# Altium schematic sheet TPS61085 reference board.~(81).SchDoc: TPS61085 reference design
size A4; Date: Not shown in title block; ApprovedBy: Not shown in title block; CheckedBy: Not shown in title block; Author: Not shown in title block; CompanyName: Not shown in title block; DrawnBy: Helen Chen; Engineer: Not shown in title block; Organization: Not shown in title block; Address1: Not shown in title block; Address2: Not shown in title block; Address3: Not shown in title block; Address4: Not shown in title block; DocumentNumber: 1; Revision: Use project parameter SCH_Rev; SheetNumber: 1; SheetTotal: 2; PageSetup: Record=PageOptions¦CenterHorizontal=True¦CenterVertical=True¦PrintScale=0.91¦XCorrection=1.00¦YCorrection=1.00¦PrintKind=0¦BorderSize=5000000¦LeftOffset=0¦BottomOffset=0¦Orientation=2¦PaperLength=1000¦PaperWidth=1000¦Scale=100¦PaperSource=15¦PrintQuality=600¦MediaType=1¦DitherType=10¦PrintScaleMode=1¦PaperKind=Letter
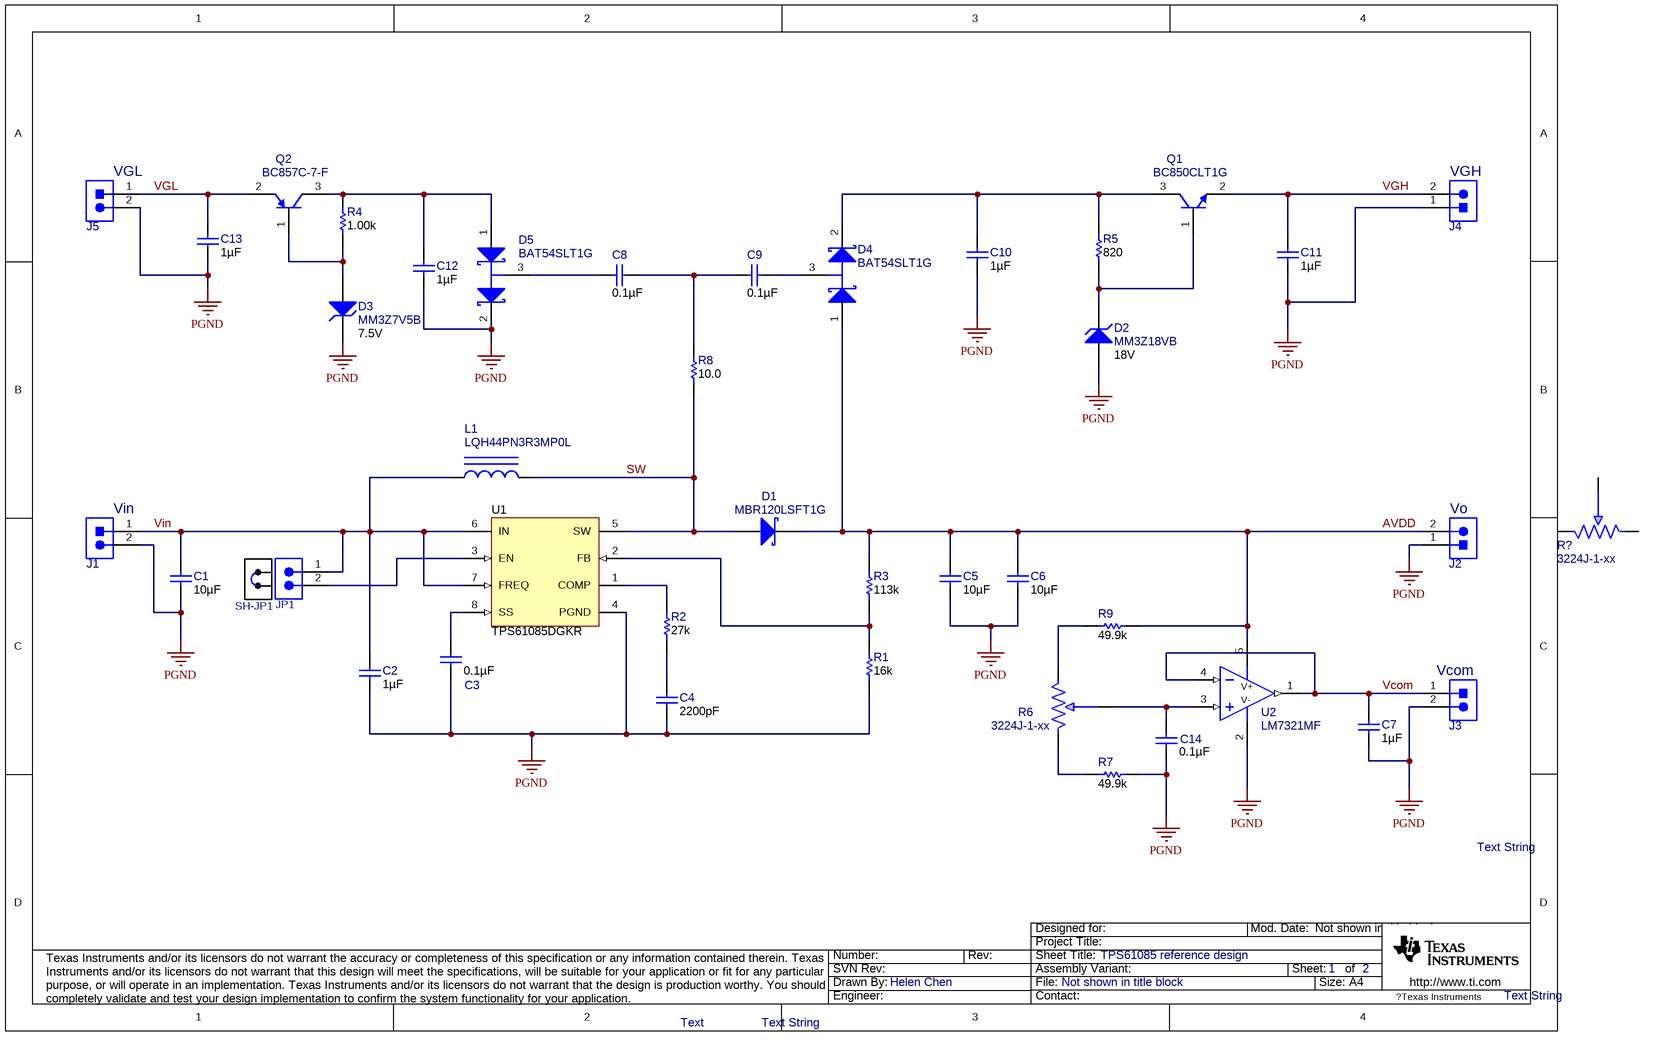
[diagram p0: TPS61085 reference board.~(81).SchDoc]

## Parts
C1  ValueDisplayed: 10µF  [0805_HV]  (hidden comment: GRM219R61A106KE44D)
C2  ValueDisplayed: 1µF  [0603]  (hidden comment: GRM185R61C105KE44D)
C3  ValueDisplayed: 0.1µF  [0402]  (hidden comment: GRM155R71C104KA88D)
C4  ValueDisplayed: 2200pF  [0402]  (hidden comment: GRM155R61C222KA01D)
C5  ValueDisplayed: 10µF  [0805_HV]  (hidden comment: C2012X5R1E106K125AB)
C6  ValueDisplayed: 10µF  [0805_HV]  (hidden comment: C2012X5R1E106K125AB)
C7  ValueDisplayed: 1µF  [0603]  (hidden comment: GRM185R61C105KE44D)
C8  ValueDisplayed: 0.1µF  [0603]  (hidden comment: 06035C104KAT2A)
C9  ValueDisplayed: 0.1µF  [0603]  (hidden comment: 06035C104KAT2A)
C10  ValueDisplayed: 1µF  [0603]  (hidden comment: GRM188R61H105KAALD)
C11  ValueDisplayed: 1µF  [0603]  (hidden comment: GRM188R61H105KAALD)
C12  ValueDisplayed: 1µF  [0603]  (hidden comment: GRM185R61C105KE44D)
C13  ValueDisplayed: 1µF  [0603]  (hidden comment: GRM185R61C105KE44D)
C14  ValueDisplayed: 0.1µF  [0402]  (hidden comment: GRM155R71C104KA88D)
D1  MBR120LSFT1G  [SOD-123FL]
D2  MM3Z18VB  value 18V  [SOD-323F]
D3  MM3Z7V5B  value 7.5V  [SOD-323F]
D4  BAT54SLT1G  [SOT-23]
D5  BAT54SLT1G  [SOT-23]
J1  ED555/2DS  [TERM_BLK_ED555-2DS]  (value not drawn)
J2  ED555/2DS  [TERM_BLK_ED555-2DS]  (value not drawn)
J3  ED555/2DS  [TERM_BLK_ED555-2DS]  (value not drawn)
J4  ED555/2DS  [TERM_BLK_ED555-2DS]  (value not drawn)
J5  ED555/2DS  [TERM_BLK_ED555-2DS]  (value not drawn)
JP1  PEC02SAAN  [CONN_PEC02SAAN]  (value not drawn)
L1  LQH44PN3R3MP0L  [IND_LQH44P]
Q1  BC850CLT1G  [SOT-23]
Q2  BC857C-7-F  [SOT-23]
R1  ValueDisplayed: 16k  [0402]  (hidden comment: CRCW040216K0JNED)
R2  ValueDisplayed: 27k  [0402]  (hidden comment: CRCW040227K0JNED)
R3  ValueDisplayed: 113k  [0402]  (hidden comment: CRCW0402113KFKED)
R4  ValueDisplayed: 1.00k  [0603]  (hidden comment: RC0603FR-071KL)
R5  ValueDisplayed: 820  [0603]  (hidden comment: RC0603FR-07820RL)
R6  3224J-1-xx  [POT_2MM-SQ]
R7  ValueDisplayed: 49.9k  [0402]  (hidden comment: CRCW040249K9FKED)
R8  ValueDisplayed: 10.0  [0603]  (hidden comment: CRCW060310R0FKEA)
R9  ValueDisplayed: 49.9k  [0402]  (hidden comment: CRCW040249K9FKED)
R?  3224J-1-xx  [POT_2MM-SQ]
SH-JP1  969102-0000-DA  [SNT-100-BK-G]  (value not drawn)
U1  TPS61085DGKR  [DGK0008A_N]
U2  LM7321MF  [MF05A_L]

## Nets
PGND: C1.2 C2.2 C3.2 C4.2 C5.2 C6.2 C7.2 C10.2 C11.2 C12.2 C13.2 C14.2 D2.2(A) D3.1(K) D5.2(K) J1.2 J2.1 J3.2 J4.1 J5.2 R1.1 R7.2 U1.4(PGND) U2.2(V-)
AVDD: C5.1 C6.1 D1.1(K) D4.1(A) J2.2 R3.2 R9.2 U2.5(V+)
SW: D1.2(A) L1.2 R8.1 U1.5(SW)
Vcom: C7.1 J3.1 U2.1(OUT) U2.4(IN-)
VGH: C11.1 J4.2 Q1.2(E)
VGL: C13.1 J5.1 Q2.2(E)
Vin: C1.1 C2.1 J1.1 JP1.1 L1.1 U1.6(IN) U1.7(FREQ)
NetC3_1: C3.1 U1.8(SS)
NetC4_1: C4.1 R2.1
NetC8_1: C8.1 C9.2 R8.2
NetC8_2: C8.2 D5.3(C)
NetC9_1: C9.1 D4.3(C)
NetC10_1: C10.1 D4.2(K) Q1.3(C) R5.2
NetC12_1: C12.1 D5.1(A) Q2.3(C) R4.2
NetC14_1: C14.1 R6.2 U2.3(IN+)
NetD2_1: D2.1(K) Q1.1(B) R5.1
NetD3_2: D3.2(A) Q2.1(B) R4.1
NetJP1_2: JP1.2 U1.3(EN)
NetR1_2: R1.2 R3.1 U1.2(FB)
NetR2_2: R2.2 U1.1(COMP)
NetR6_1: R6.1 R9.1
NetR6_3: R6.3 R7.1

Not connected (* = marked no-connect by the designer): R? 1 2 3

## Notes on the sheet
- (near J5) VGL
- (near J4) VGH
- (near J1) Vin
- (near J2) Vo
- (near J3) Vcom
- Text String
- Text

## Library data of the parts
C1 = GRM219R61A106KE44D: CAP, CERM, 10 µF, 10 V, +/- 10%, X5R, 0805; Manufacturer: MuRata; Polarized: N; CompType: Capacitor; Value: 10uF; U/M: EA; Cap_F: 0.00001; Tolerance_%: 10; ESR_ohm: 0.005; Value1: 0.005 ohm; Value2: 10V; TaMin_C: -55; TaMax_C: 85; Cap_Case: 0805
C2 C7 C12 C13 = GRM185R61C105KE44D: CAP, CERM, 1 µF, 16 V, +/- 10%, X5R, 0603; Manufacturer: MuRata; Polarized: N; CompType: Capacitor; Value: 1uF; U/M: EA; Cap_F: 0.000001; Tolerance_%: 10; Value1: Unknown; VDC_V: 16; Value2: 16V; TaMin_C: -55; TaMax_C: 85
C3 C14 = GRM155R71C104KA88D: CAP, CERM, 0.1 µF, 16 V, +/- 10%, X7R, 0402; Manufacturer: MuRata; Polarized: N; CompType: Capacitor; Value: 0.1uF; U/M: EA; Cap_F: 0.0000001; Tolerance_%: 10; Value1: Unknown; VDC_V: 16; Value2: 16V; TaMin_C: -55; TaMax_C: 125
C4 = GRM155R61C222KA01D: CAP, CERM, 2200 pF, 16 V, +/- 10%, X5R, 0402; Manufacturer: MuRata; Polarized: N; CompType: Capacitor; Value: 2200pF; U/M: EA; Cap_F: 0.0000000022; Tolerance_%: 10; Value1: Unknown; VDC_V: 16; Value2: 16V; TaMin_C: -55; TaMax_C: 85
C5 C6 = C2012X5R1E106K125AB: CAP, CERM, 10 µF, 25 V, +/- 10%, X5R, 0805; Manufacturer: TDK; Polarized: N; CompType: Capacitor; Value: 10uF; U/M: EA; Cap_F: 0.00001; Tolerance_%: 10; Value1: Unknown; VDC_V: 25; Value2: 25V; TaMin_C: -55; TaMax_C: 85; Cap_Case: 0805
C8 C9 = 06035C104KAT2A: CAP, CERM, 0.1 µF, 50 V, +/- 10%, X7R, 0603; Manufacturer: AVX; Polarized: N; CompType: Capacitor; Value: 0.1uF; U/M: EA; Cap_F: 0.0000001; Tolerance_%: 10; Value1: Unknown; VDC_V: 50; Value2: 50V; TaMin_C: -55; TaMax_C: 125
C10 C11 = GRM188R61H105KAALD: CAP, CERM, 1 µF, 50 V, +/- 10%, X5R, 0603; Manufacturer: MuRata; Polarized: N; CompType: Capacitor; Value: 1uF; U/M: EA; Cap_F: 0.000001; Tolerance_%: 10; Value1: Unknown; VDC_V: 50; Value2: 50V; TaMin_C: -55; TaMax_C: 85
D1 = MBR120LSFT1G: Diode, Schottky, 20 V, 1 A, SOD-123FL; Manufacturer: ON Semiconductor; U/M: EA; Vf_V: 0.45; Value: 20V; Value1: 1A; Value2: 0.45V; Io_A: 1; Vr_V: 20; TJmax_C: 125; RJC_CperW: 26
D2 = MM3Z18VB: Diode, Zener, 18 V, 200 mW, SOD-323F; Manufacturer: Fairchild Semiconductor; SymbolCreator: a0412235; U/M: EA; Power_W: 0.2; Vz_V: 18; Value1: 0.2W; RJA_CperW: 595
D3 = MM3Z7V5B: Diode, Zener, 7.5 V, 200 mW, SOD-323F; Manufacturer: Fairchild Semiconductor; SymbolCreator: a0412235; U/M: EA; Power_W: 0.2; Vz_V: 7.5; Value1: 0.2W; RJA_CperW: 595
D4 D5 = BAT54SLT1G: Diode, Schottky, 30 V, 0.2 A, SOT-23; Manufacturer: ON Semiconductor; U/M: EA; Vf_V: 0.8; Value: 30V; Value1: 0.2A; Value2: 0.8V; Io_A: 0.2; Vr_V: 30; TJmax_C: 150
J1-J5 = ED555/2DS: Terminal Block, 6A, 3.5mm Pitch, 2-Pos, TH; Manufacturer: On-Shore Technology; SymbolCreator: a0412235; CompType: Connector; U/M: EA
JP1 = PEC02SAAN: Header, 100mil, 2x1, Tin plated, TH; Manufacturer: Sullins Connector Solutions; SymbolCreator: a0412235; U/M: EA
L1 = LQH44PN3R3MP0L: Inductor, Shielded Drum Core, Ferrite, 3.3 µH, 1.77 A, 0.065 ohm, SMD; Manufacturer: MuRata; Value: 3.3uH; Ind_H: 3.3E-6; ValueDisplayed: 3.3µH; Imax_A: 1.77; Irms: 1.77A @ 40C rise; Isat: 2.1A @ 30% inductance drop; DCR_ohm: 0.065; Value2: 1.77A
Q1 = BC850CLT1G, ON Semiconductor: Transistor, NPN, 45 V, 0.1 A, SOT-23; CompType: BJT; PNP: 0; NPN: 1; Vceo_V: 45; Vcesat1_V: 0.7; Value: 45 V; IcRated_A: 0.1; Value1: 0.1 A; HfeMax: 800; TaMin_C: -55; TaMax_C: 150; U/M: EA
Q2 = BC857C-7-F, Diodes Inc.: Transistor, PNP, 45 V, 0.1 A, SOT-23; CompType: BJT; PNP: 1; NPN: 0; Vceo_V: 45; Vcesat1_V: 0.075; Value: 45 V; IcRated_A: 0.1; Value1: 0.1 A; HfeMax: 600; TaMin_C: -65; TaMax_C: 150; U/M: EA
R1 = CRCW040216K0JNED: RES, 16 k, 5%, 0.063 W, 0402; Manufacturer: Vishay-Dale; CompType: Resistor; Value: 16k; Res_ohm: 16000; Value_Code: 16k0; Tolerance_%: 5; Power_W: 0.063; Value2: 0.063W; VDC_V: 50; TempCo: 200 ppm/C; EIA_Code: E24; U/M: EA
R2 = CRCW040227K0JNED: RES, 27 k, 5%, 0.063 W, 0402; Manufacturer: Vishay-Dale; CompType: Resistor; Value: 27k; Res_ohm: 27000; Value_Code: 27k0; Tolerance_%: 5; Power_W: 0.063; Value2: 0.063W; VDC_V: 50; TempCo: 200 ppm/C; EIA_Code: E24; U/M: EA
R3 = CRCW0402113KFKED: RES, 113 k, 1%, 0.063 W, 0402; Manufacturer: Vishay-Dale; CompType: Resistor; Value: 113k; Res_ohm: 113000; Tolerance_%: 1; Power_W: 0.063; Value2: 0.063W; VDC_V: 50; TempCo: 100 ppm/C; EIA_Code: E96; U/M: EA
R4 = RC0603FR-071KL: RES, 1.00 k, 1%, 0.1 W, 0603; Manufacturer: Yageo America; CompType: Resistor; Value: 1.00k; Res_ohm: 1000; Value_Code: 1k00; Tolerance_%: 1; Power_W: 0.1; Value2: 0.1W; VDC_V: 150; TempCo: 200 ppm/C; EIA_Code: E96; U/M: EA
R5 = RC0603FR-07820RL: RES, 820, 1%, 0.1 W, 0603; Manufacturer: Yageo America; CompType: Resistor; Value: 820; Value_Code: 820R; Tolerance_%: 1; Power_W: 0.1; Value2: 0.1W; VDC_V: 150; TempCo: 200 ppm/C; U/M: EA
R6 R? = POT_3312_SERIES: Potentiometer,  2 mm SMDTop-Adjust; Manufacturer: Bourns; Area: 12.6 mm; Value: xx K
R7 R9 = CRCW040249K9FKED: RES, 49.9 k, 1%, 0.063 W, 0402; Manufacturer: Vishay-Dale; CompType: Resistor; Value: 49.9k; Res_ohm: 49900; Value_Code: 49k9; Tolerance_%: 1; Power_W: 0.063; Value2: 0.063W; VDC_V: 50; TempCo: 100 ppm/C; EIA_Code: E96; U/M: EA
R8 = CRCW060310R0FKEA: RES, 10.0, 1%, 0.1 W, 0603; Manufacturer: Vishay-Dale; CompType: Resistor; Value: 10.0; Res_ohm: 10; Value_Code: 10R0; Tolerance_%: 1; Power_W: 0.1; Value2: 0.1W; VDC_V: 75; TempCo: 100 ppm/C; EIA_Code: E96; U/M: EA
SH-JP1 = 969102-0000-DA: Shunt, 100mil, Gold plated, Black; Manufacturer: 3M; Alternate Manufacturer: Samtec; Value: 1x2; Note: You can "mate" this to a header by matching the designator.  i.e. use SH-J3 for header J3
U1 = TPS61085DGKR: 18.5 V, 2 A, 650 KHz / 1.2 MHz Step-Up DC-DC Converter with Forced PWM Mode, 2.3 to 6 V, -40 to 85 degC, 8-pin SOP (DGK8), Green (RoHS & no Sb/Br); Manufacturer: Texas Instruments; Alternate Manufacturer: None; Alternate PartNumber: Equivalent; Iout(Max)(A): 2; Iq(Typ)(mA): 0.07; Rating: Catalog; SubFamily: White LED Driver; Switching Frequency(Typ)(kHz): 650, 1200; Topology: Boost; Vin(Max)(V): 6; Vin(Min)(V): 2.3
U2 = LM7321MF: Single 30V High Output Current and Unlimited Capacitive Load Op Amp; Manufacturer: National Semiconductor; Characteristics: LM7321MF Single 30V High Output Current and Unlimited Capacitive Load Op Amp; CompType: OpAmp IC; TaMin_C: -40.0; TaMax_C: 125.0; PowerWise: Y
